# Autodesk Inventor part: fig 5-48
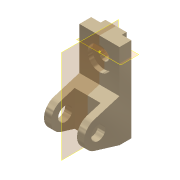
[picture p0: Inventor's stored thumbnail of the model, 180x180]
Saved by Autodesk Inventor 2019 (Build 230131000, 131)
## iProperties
Shininess: 65.0
Angle Display Precision: 2
Document Length Units: 11269
Document Angle Units: 11279
Document Time Units: 11290
Document Mass Units: 11283
Document Length Units Precision: 3
Document Angle Units Precision: 2
Created: 2001-11
Part Number: fig 5-48
Document SubType Name: Modeling
Designer: Renu Muthoo
Density: 1 g/cm^3
Material: Generic
Appearance: Metal-Titanium (Polished)
Density: 0.0
Volumn: 0.0
Area: 0.0
PropertySet Name: Model Information
Control State: 0
Master: False
Checked Out: False
Author: Renu Muthoo
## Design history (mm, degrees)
node "Sketch1"
sketch "Sketch2"
  geometry: L1 (33.257, 104.664)-(33.257, -75.336); L2 (33.257, -75.336)-(8.257, -75.336); L3 (8.257, -75.336)-(-45.451, -59.045); L4 (-45.451, -1.628)-(8.257, 14.664); L5 (8.257, 14.664)-(8.257, 104.664); L6 (8.257, 104.664)-(33.257, 104.664); C1 r 15 at (-36.743, -30.336); A1 r 30 centre (-36.743, -30.336) between (-45.451, -1.628) and (-45.451, -59.045)
  constraints: 12 end point, 2 centre point, 2 equal length, 2 parallel, 2 point on circle, 2 tangent, 1 coincident, 1 perpendicular, 1 vertical
  dimensions: "d0" = 180 distance of L1.start L1.end; "d1" = 30 radius of A1; "d2" = 25 distance of L5.end L1.start; "d3" = 45 distance from line of L2 A1.centre; "d4" = 70 distance from line of L1 A1.centre; "d5" = 30 diameter of C1
extrude "Extrusion1" new body sketch "Sketch2" distance "d6" = 85; taper "d7" = 0 deg
workplane "Work Plane1"
sketch "Sketch3"
  geometry: L1 (15, 62.364)-(70, 62.364); L2 (70, 62.364)-(70, -52.386); L3 (70, -52.386)-(15, -52.386); L4 (15, -52.386)-(15, 62.364); L5 (0, -45)-(0, -28.708) reference
  constraints: 8 end point, 2 parallel, 1 horizontal, 1 perpendicular
  dimensions: "d8" = 55 distance of L1.start L1.end; "d9" = 15 distance between parallel lines of L5 L4
extrude "Extrusion2" cut sketch "Sketch3" distance "d10" = 50; taper "d11" = 0 deg
sketch "Sketch4"
  geometry: L1 (0, 25)-(85, 25) reference; L2 (0, 0)-(0, 25) reference; L3 (20, 25)-(65, 25); L4 (65, 25)-(65, 35); L5 (65, 35)-(20, 35); L6 (20, 35)-(20, 25)
  constraints: 8 end point, 2 parallel, 1 horizontal, 1 perpendicular, 1 point on line
  dimensions: "d12" = 45 distance of L4.end L5.end; "d13" = 10 distance of L3.end L4.end; "d14" = 20 distance between parallel lines of L2 L6
extrude "Extrusion3" join sketch "Sketch4" stored distance "d15" = 50; taper "d16" = 0 deg
sketch "Sketch5"
  geometry: L1 (85, 0)-(85, 90) reference; L2 (0, 90)-(85, 90) reference; 1 further point
  dimensions: "d17" = 42 distance from line of L2 point (42.5, 48); "d18" = 42.5 distance from line of L1 point (42.5, 48)
hole "Hole1" sketch "Sketch5" at (42.5, 48) diameter "d19" = 20; stored, may be unused: countersink angle "d23" = 82 deg, drill point angle "d25" = 118 deg; dims "d20" = 6, "d21" = 50, "d22" = 10, "d24" = 8
workpoint "Work Point9"
  workplane "Work Plane8"
  workplane "Work Plane12"
body "Solid1"
